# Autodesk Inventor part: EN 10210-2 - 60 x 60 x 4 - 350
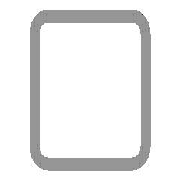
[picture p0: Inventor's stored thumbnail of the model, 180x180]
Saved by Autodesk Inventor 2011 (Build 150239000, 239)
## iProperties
_CCFamilyMember: 21
_CCFamilyDisplayName: DIN EN 10210-2 (Square) - Tube
_FrameMemberDoc: Frame Member File
_Version: 15.0.0
_GetPNFromCC: 1
Created: 2010-02
Part Number: EN 10210-2 - 60 x 60 x 4 - 350
Material: Steel, Mild
Description: Tube 60*60*4
Document SubType Name: Modeling
Standard: DIN
Designer: PC
Standard Revision: 1997
Standards Organization: DIN
Language: en-US
Size Designation: 60 x 60 x 4
Categories: <MemberInstance><Categories><Category DisplayName="Structural Shapes" InternalName="089c4875-fa83-4c05-b084-43b9cc11f5ed" Mnemonic="GRDR"><CategoryParameter Dis
Stock Number: 60 x 60 x 4
Density: 7.86 g/cm^3
IsCustomPart: 1
G_L: 350.000 mm
G_W: 60.000 mm
G_H: 60.000 mm
Author: PC
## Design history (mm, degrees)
node "Start plane"
node "End plane"
sketch "Sketch"
  geometry: L1 (-30, -24)-(-30, 24); L2 (-24, 30)-(24, 30); L3 (30, 24)-(30, -24); L4 (24, -30)-(-24, -30); L5 (-24, 26)-(24, 26); L6 (26, 24)-(26, -24); L7 (24, -26)-(-24, -26); L8 (-26, -24)-(-26, 24); L9 (0, 43.74)-(0, -43.74) reference; L10 (-43.74, 0)-(43.74, 0) reference; A1 r 6 centre (-24, -24) between (-30, -24) and (-24, -30); A2 r 6 centre (-24, 24) between (-24, 30) and (-30, 24); A3 r 6 centre (24, 24) between (30, 24) and (24, 30); A4 r 6 centre (24, -24) between (24, -30) and (30, -24); A5 r 2 centre (-24, 24) between (-24, 26) and (-26, 24); A6 r 2 centre (24, 24) between (26, 24) and (24, 26); A7 r 2 centre (24, -24) between (24, -26) and (26, -24); A8 r 2 centre (-24, -24) between (-26, -24) and (-24, -26)
  constraints: 16 end point, 16 point on circle, 8 centre point, 8 tangent, 4 parallel, 3 equal radius, 2 perpendicular, 7 other
  dimensions: "d7" = 6 radius of A1 (= G_IR); "d10" = 60 distance between parallel lines of L2 L4 (= G_H); "d11" = 60 distance between parallel lines of L1 L3 (= G_W); "d12" = 4 distance between parallel lines of L3 L6 (= G_T); "d15" = 30 distance between parallel lines of L2 L10 (= 0.5 x d10); "d16" = 30 distance between parallel lines of L9 L3 (= 0.5 x d11)
extrude "Body" new body sketch "Sketch" stored distance "d3" = 350 (= G_L); taper "d4" = 0 deg
node "Driven Length"
  sketch "Sketch3"
    geometry: L1 (0, 0)-(10, 0) reference
    constraints: 2 end point, 1 horizontal
  workplane "Work Plane3"
  sketch "Sketch4"
    geometry: L1 (-2, 0)-(12, 0) reference; L2 (-2, 350)-(12, 350) reference
    dimensions: "d18" = 350 distance between parallel lines of L1 L2 (derived)
body "Solid1"
other parameters: "G_W" = 60 [user parameter; used in 1 equation term], "G_H" = 60 [user parameter; used in 1 equation term], "G_T" = 4 [user parameter; used in 1 equation term], "G_IR" = 6 [user parameter; used in 1 equation term], "G_L" = 350 (= d18) [user parameter; used in 1 equation term], "G_OFFSET_START" = 0 [user parameter; used in 1 equation term], "G_OFFSET_END" = 0 [user parameter; used in 1 equation term], "d13" = 0 (computed from G_OFFSET_START), "d17" = 90 deg
